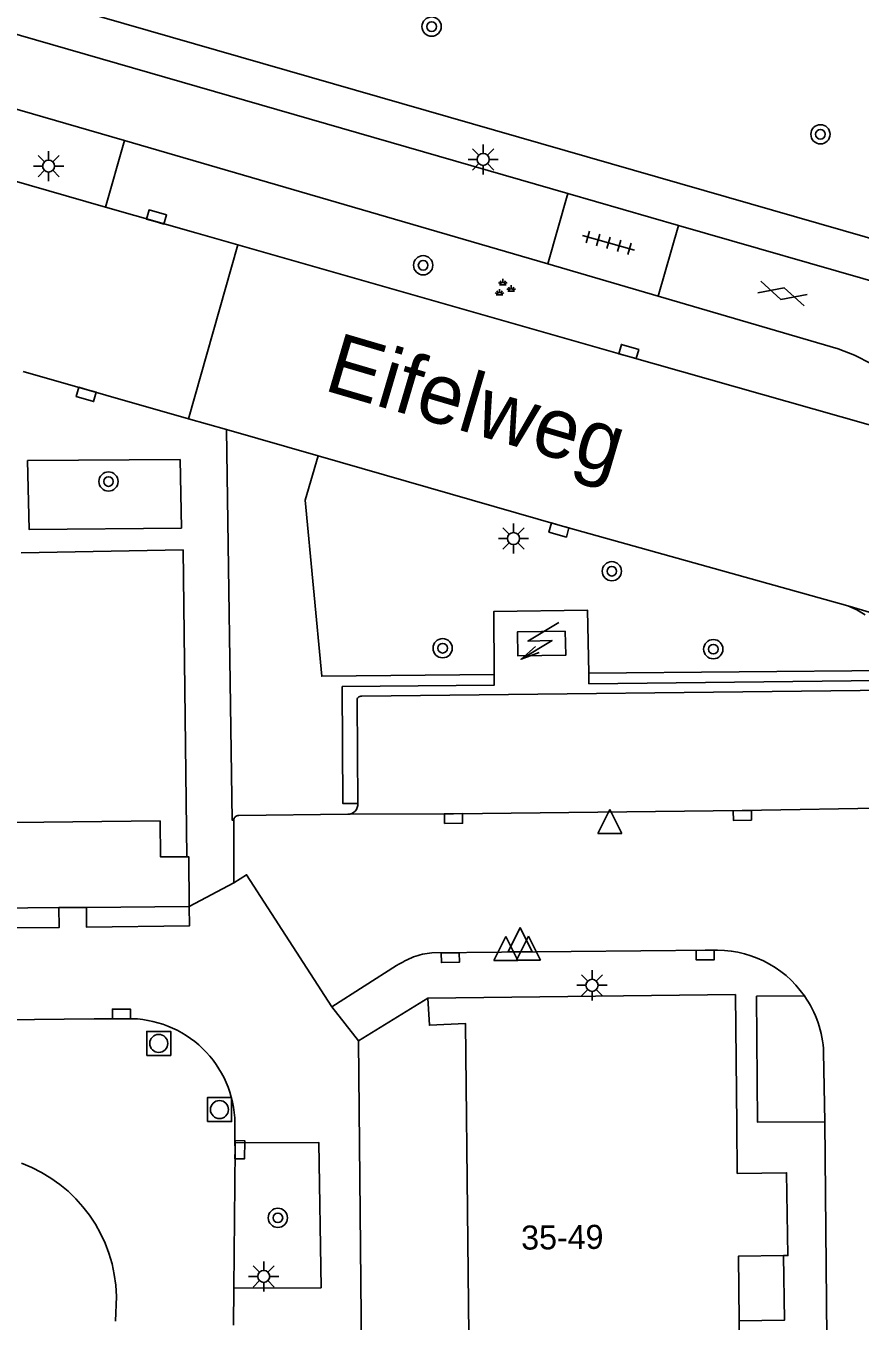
# Model space of a CAD drawing. Extents: x 132994 to 136000, y 393499 to 395512.
# Drawn here: x 133998.2 to 134032.8, y 394602.4 to 394656.2 of the extents above; entities that cross this region are included whole.
import ezdxf

# ---------------------------------------------------------------- set-up
doc = ezdxf.new("R2010")
doc.units = 0
for name, color, linetype in [('gg-afsc-erfafscheiding', 7, 'Continuous'), ('gg-anno-huisnummerreeks BGT', 7, 'Continuous'), ('gg-anno-openbare ruimte label', 7, 'Continuous'), ('gg-bbg-hoofdgebouw', 7, 'Continuous'), ('gg-bbg-lage trafo', 7, 'Continuous'), ('gg-bbg-luifel en loopbrug', 7, 'Continuous'), ('gg-knt-verharding', 7, 'Continuous'), ('gg-knt-verharding nz', 7, 'Continuous'), ('gt-grn-groengrens', 7, 'Continuous'), ('gt-grn-weggrens', 7, 'Continuous'), ('gt-symb-boom', 7, 'Continuous'), ('gt-symb-gesloten verharding', 7, 'Continuous'), ('gt-symb-groenvak', 7, 'Continuous'), ('gt-symb-kolk', 7, 'Continuous'), ('gt-symb-lichtmast', 7, 'Continuous'), ('gt-symb-rioolschacht', 7, 'Continuous'), ('gt-symb-tegel verharding', 7, 'Continuous'), ('gt-symb-trafo symbool', 7, 'Continuous'), ('gt-symb-waterafsluiter', 7, 'Continuous')]:
    doc.layers.add(name, color=color, linetype=linetype)

# ---------------------------------------------------------------- blocks, each defined once
blk = doc.blocks.new('gt0-LMAST')
at = {"layer": 'gt-symb-lichtmast'}
for p, q in [((-0.005, 0.246), (-0.005, 0.621)), ((-0.182, 0.173), (-0.447, 0.438)), ((0.172, 0.173), (0.437, 0.438)), ((-0.255, -0.004), (-0.63, -0.004)), ((-0.182, -0.181), (-0.447, -0.446)), ((-0.005, -0.254), (-0.005, -0.629)), ((0.437, -0.446), (0.172, -0.181)), ((0.245, -0.004), (0.62, -0.004))]:
    blk.add_line(p, q, dxfattribs=at)
blk.add_circle((-0.005, -0.004), 0.25, dxfattribs=at)
blk = doc.blocks.new('gt0-KOLK')
at = {"layer": 'gt-symb-kolk'}
blk.add_lwpolyline([(0, 0), (0.375, 0), (0.375, 0.4), (-0.375, 0.4), (-0.375, 0), (0, 0)], dxfattribs=at)
blk = doc.blocks.new('gt0-GESVH1')
at = {"layer": 'gt-symb-gesloten verharding'}
for p, q in [((-0.992, -0.261), (0.008, 0.239)), ((0.008, -0.261), (-0.992, 0.239)), ((0.008, 0.239), (1.008, -0.261)), ((1.008, 0.239), (0.008, -0.261))]:
    blk.add_line(p, q, dxfattribs=at)
blk = doc.blocks.new('gt0-GRVAK')
at = {"layer": 'gt-symb-groenvak'}
for p, q in [((-0.11, 0.189), (-0.228, 0.24)), ((-0.182, 0.153), (0.088, 0.153)), ((-0.091, 0.211), (-0.156, 0.322)), ((-0.047, 0.214), (-0.047, 0.393)), ((-0.004, 0.211), (0.061, 0.322)), ((0.015, 0.189), (0.133, 0.24)), ((0.262, -0.052), (0.197, 0.059)), ((0.305, -0.049), (0.305, 0.13)), ((0.349, -0.052), (0.414, 0.059)), ((-0.245, -0.228), (-0.363, -0.177)), ((-0.318, -0.264), (-0.047, -0.264)), ((-0.226, -0.206), (-0.291, -0.095)), ((-0.183, -0.203), (-0.183, -0.024)), ((-0.139, -0.206), (-0.074, -0.095)), ((-0.12, -0.228), (-0.002, -0.177)), ((0.243, -0.074), (0.125, -0.023)), ((0.17, -0.11), (0.441, -0.11)), ((0.368, -0.074), (0.486, -0.023))]:
    blk.add_line(p, q, dxfattribs=at)
blk = doc.blocks.new('gt0-BOOM')
at = {"layer": 'gt-symb-boom'}
for radius in [0.4, 0.2]:
    blk.add_circle((0, 0), radius, dxfattribs=at)
blk = doc.blocks.new('gt0-TEG1')
at = {"layer": 'gt-symb-tegel verharding'}
for p, q in [((-1.125, 0), (1.125, 0)), ((-0.9, -0.25), (-0.9, 0.25)), ((-0.45, -0.25), (-0.45, 0.25)), ((0, -0.25), (0, 0.25)), ((0.45, -0.25), (0.45, 0.25)), ((0.9, -0.25), (0.9, 0.25))]:
    blk.add_line(p, q, dxfattribs=at)
blk = doc.blocks.new('gt0-HSP')
at = {"layer": 'gt-symb-trafo symbool'}
for points in [[(0.771, 0.746), (-0.529, -0.004), (0.471, -0.004), (-0.829, -0.754)], [(-0.217, -0.24), (-0.829, -0.754), (-0.077, -0.48)]]:
    blk.add_lwpolyline(points, dxfattribs=at)
blk = doc.blocks.new('gt0-WAFSL')
at = {"layer": 'gt-symb-waterafsluiter'}
for p, q in [((-0.5, -0.333), (0, 0.667)), ((0, 0.667), (0.5, -0.333)), ((0.5, -0.333), (-0.5, -0.333))]:
    blk.add_line(p, q, dxfattribs=at)
blk = doc.blocks.new('gt0-RS')
at = {"layer": 'gt-symb-rioolschacht'}
blk.add_lwpolyline([(-0.5, -0.5), (0.5, -0.5), (0.5, 0.5), (-0.5, 0.5)], close=True, dxfattribs=at)
blk.add_circle((0, 0), 0.375, dxfattribs=at)

msp = doc.modelspace()

# ---------------------------------------------------------------- linework, layer by layer
at = {"layer": 'gg-afsc-erfafscheiding'}
msp.add_line((134014.871, 394615.77), (134011.98, 394613.999), dxfattribs=at)
at = {"layer": 'gg-bbg-hoofdgebouw'}
for p, q in [((134004.7, 394634.396), (133997.971, 394634.277)), ((134004.704, 394634.396), (134004.7, 394634.396)), ((134004.85, 394621.65), (134004.704, 394634.396)), ((134027.64, 394615.92), (134014.871, 394615.77)), ((134027.698, 394610.51), (134027.64, 394615.92)), ((134027.881, 394595.94), (134027.803, 394602.364))]:
    msp.add_line(p, q, dxfattribs=at)
for points in [[(133984.752, 394621.42), (133985.62, 394621.43), (133985.6, 394622.93), (134003.74, 394623.14), (134003.76, 394621.64), (134004.85, 394621.65)], [(134014.871, 394615.77), (134014.93, 394614.65), (134016.43, 394614.72), (134016.63, 394596.61), (134015.13, 394596.6), (134015.135, 394595.804)], [(134029.636, 394605.077), (134029.82, 394605.08), (134029.77, 394608.52), (134027.72, 394608.49), (134027.698, 394610.51)], [(134027.803, 394602.364), (134027.77, 394605.05), (134029.636, 394605.077)]]:
    msp.add_lwpolyline(points, dxfattribs=at)
at = {"layer": 'gg-bbg-lage trafo'}
msp.add_lwpolyline([(134020.576, 394631.028), (134020.598, 394630.03), (134018.606, 394629.994), (134018.587, 394630.993), (134020.576, 394631.028)], dxfattribs=at)
at = {"layer": 'gg-bbg-luifel en loopbrug'}
msp.add_lwpolyline([(134029.636, 394605.077), (134029.675, 394602.387), (134027.803, 394602.364)], dxfattribs=at)
at = {"layer": 'gg-knt-verharding'}
for p, q in [((134035.154, 394646.792), (133977.504, 394663.407)), ((134002.264, 394651.418), (133978.567, 394658.236)), ((134002.264, 394651.418), (134001.469, 394648.639)), ((134019.847, 394646.281), (134002.264, 394651.418)), ((134020.679, 394649.206), (134019.847, 394646.281)), ((134025.282, 394647.882), (134020.679, 394649.206)), ((134005.232, 394647.568), (134001.469, 394648.639)), ((134005.232, 394647.568), (134006.97, 394647.072)), ((134024.44, 394644.939), (134025.282, 394647.882)), ((134025.282, 394647.882), (134034.947, 394645.101)), ((134024.44, 394644.939), (134019.847, 394646.281)), ((134004.917, 394639.851), (133998.06, 394641.815)), ((134006.501, 394639.397), (134004.917, 394639.851)), ((134010.306, 394638.305), (134006.501, 394639.397)), ((133998.237, 394638.112), (134004.57, 394638.161)), ((134004.57, 394638.161), (134004.637, 394635.298)), ((134032.315, 394632.074), (134038.743, 394630.179)), ((134012.118, 394628.326), (134034.069, 394628.573)), ((134011.959, 394623.865), (134011.923, 394628.127)), ((134007.013, 394623.36), (134011.54, 394623.414)), ((134006.805, 394623.172), (134006.804, 394620.56)), ((133999.537, 394619.536), (133991.79, 394619.461)), ((134000.681, 394619.547), (133999.537, 394619.536)), ((134004.951, 394619.589), (134000.681, 394619.547)), ((134026.612, 394617.765), (134015.036, 394617.652)), ((134010.871, 394615.417), (134013.57, 394617.137)), ((134011.98, 394613.999), (134012.594, 394555.839)), ((134031.353, 394610.634), (134031.306, 394613.525)), ((134006.85, 394610.588), (134006.854, 394609.762)), ((134001.891, 394602.346), (134001.932, 394603.382)), ((134006.787, 394602.181), (134006.801, 394603.729))]:
    msp.add_line(p, q, dxfattribs=at)
for points in [[(133944.152, 394670.878), (133957.688, 394667.259), (133972.139, 394663.219), (133979.851, 394661.005), (134020.679, 394649.206)], [(134001.469, 394648.639), (133983.972, 394653.681), (133977.713, 394655.453)], [(134006.97, 394647.072), (134023.157, 394642.45), (134035.403, 394638.976)], [(134034.073, 394641.901), (134033.291, 394642.131), (134032.591, 394642.496), (134031.911, 394642.756), (134024.44, 394644.939)], [(134006.805, 394623.172), (134006.733, 394623.171), (134006.501, 394639.397)], [(134032.315, 394632.074), (134020.366, 394635.42), (134010.306, 394638.305)], [(134004.637, 394635.298), (133998.303, 394635.249), (133998.237, 394638.112)], [(134021.55, 394629.284), (134021.497, 394631.897), (134017.61, 394631.846), (134017.62, 394629.225)], [(134033.03, 394631.697), (134032.684, 394631.91), (134032.315, 394632.074)], [(134017.62, 394629.225), (134017.622, 394628.781), (134011.309, 394628.718), (134011.336, 394623.861), (134011.959, 394623.865)], [(134021.55, 394629.284), (134021.559, 394628.835), (134034.871, 394628.993), (134034.985, 394620.906), (134034.39, 394620.898)], [(134004.951, 394619.589), (134004.932, 394621.651), (134004.85, 394621.65)], [(134006.804, 394620.56), (134007.337, 394620.9), (134010.871, 394615.417)], [(133999.537, 394619.536), (133999.547, 394618.709), (133991.798, 394618.649), (133991.79, 394619.461)], [(134004.951, 394619.589), (134004.958, 394618.774), (134000.69, 394618.723), (134000.681, 394619.547)], [(134031.353, 394610.634), (134028.563, 394610.619), (134028.522, 394615.853), (134030.51, 394615.868)], [(133997.279, 394614.871), (134001.009, 394614.914), (134002.367, 394614.921)], [(134006.801, 394603.729), (134010.428, 394603.741), (134010.336, 394609.777), (134006.854, 394609.762)], [(134006.801, 394603.729), (134006.855, 394609.479), (134006.854, 394609.762)]]:
    msp.add_lwpolyline(points, dxfattribs=at)
for centre, radius, start, end in [((134012.102, 394628.146), 0.18, 84.9912, 186.1721), ((134011.532, 394623.841), 0.427, 271.0341, 3.1789), ((134006.996, 394623.17), 0.191, 84.7737, 179.4437), ((134019.257, 394606.774), 11.821, 114.9601, 118.7587), ((134015.273, 394614.616), 3.046, 94.4627, 109.2468), ((134026.86, 394613.321), 4.45, 34.9035, 93.1959), ((134026.858, 394613.321), 4.453, 2.6313, 34.8976), ((134002.451, 394610.522), 4.4, 0.8595, 91.09), ((133995.88, 394603.241), 6.054, 1.3392, 69.6421)]:
    msp.add_arc(centre, radius, start, end, dxfattribs=at)
at = {"layer": 'gg-knt-verharding nz'}
for points in [[(134011.54, 394623.414), (134015.93, 394623.439), (134027.929, 394623.566), (134034.337, 394623.676)], [(134031.291, 394601.675), (134031.44, 394601.677), (134031.353, 394610.634)]]:
    msp.add_lwpolyline(points, dxfattribs=at)
at = {"layer": 'gt-grn-groengrens'}
msp.add_line((134021.55, 394629.284), (134035.497, 394629.396), dxfattribs=at)
msp.add_lwpolyline([(134010.306, 394638.305), (134009.763, 394636.46), (134010.457, 394629.151), (134017.62, 394629.225)], dxfattribs=at)
at = {"layer": 'gt-grn-weggrens'}
for p, q in [((134006.97, 394647.072), (134004.917, 394639.851)), ((134004.951, 394619.589), (134006.804, 394620.56)), ((134010.871, 394615.417), (134011.98, 394613.999))]:
    msp.add_line(p, q, dxfattribs=at)

# ---------------------------------------------------------------- block references
at = {"layer": 'gt-symb-boom'}
for p in [(134015.022, 394656.144), (134014.67, 394646.227), (134001.6, 394637.241), (134022.508, 394633.514), (134015.48, 394630.315), (134026.723, 394630.275), (134008.635, 394606.645)]:
    msp.add_blockref('gt0-BOOM', p, dxfattribs=at)
at = {"layer": 'gt-symb-boom', "rotation": 164.99108632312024}
msp.add_blockref('gt0-BOOM', (134031.174, 394651.669), dxfattribs=at)
at = {"layer": 'gt-symb-gesloten verharding', "rotation": -15.843082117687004}
msp.add_blockref('gt0-GESVH1', (134029.594, 394645.064), dxfattribs=at)
at = {"layer": 'gt-symb-groenvak'}
msp.add_blockref('gt0-GRVAK', (134018.025, 394645.264), dxfattribs=at)
at = {"layer": 'gt-symb-kolk'}
for p, rotation in [((134003.54, 394648.042), -15.662106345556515), ((134023.157, 394642.45), -15.898187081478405), ((134000.728, 394641.052), 163.97589034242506), ((134020.366, 394635.42), 164.39306952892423), ((134015.93, 394623.439), -179.67721029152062), ((134027.929, 394623.566), -179.39478540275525), ((134015.798, 394617.659), -179.4351303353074), ((134026.384, 394617.763), -179.4351303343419), ((134002.14, 394614.92), 0.2501630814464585), ((134006.855, 394609.479), -90.55680061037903)]:
    msp.add_blockref('gt0-KOLK', p, dxfattribs=dict(at, rotation=rotation))
at = {"layer": 'gt-symb-lichtmast'}
for p in [(134017.167, 394650.63), (133999.118, 394650.353), (134018.429, 394634.875), (134021.69, 394616.311), (134008.051, 394604.216)]:
    msp.add_blockref('gt0-LMAST', p, dxfattribs=at)
at = {"layer": 'gt-symb-rioolschacht'}
for p in [(134003.687, 394613.892), (134006.21, 394611.144)]:
    msp.add_blockref('gt0-RS', p, dxfattribs=at)
at = {"layer": 'gt-symb-tegel verharding', "rotation": -15.898187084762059}
msp.add_blockref('gt0-TEG1', (134022.375, 394647.158), dxfattribs=at)
at = {"layer": 'gt-symb-trafo symbool', "rotation": 1.031212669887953}
msp.add_blockref('gt0-HSP', (134019.553, 394630.624), dxfattribs=at)
at = {"layer": 'gt-symb-waterafsluiter'}
for p in [(134022.43, 394622.944), (134018.106, 394617.675), (134018.705, 394618.037), (134019.052, 394617.685)]:
    msp.add_blockref('gt0-WAFSL', p, dxfattribs=at)

# ---------------------------------------------------------------- texts
at = {"layer": 'gg-anno-huisnummerreeks BGT'}
msp.add_text('35-49', height=1, rotation=0.6, dxfattribs=at).set_placement((134018.747, 394605.323))
at = {"layer": 'gg-anno-openbare ruimte label'}
msp.add_text('Eifelweg', height=2.5, rotation=343.6, dxfattribs=at).set_placement((134010.486, 394641.055))

doc.saveas('drawing.dxf')
